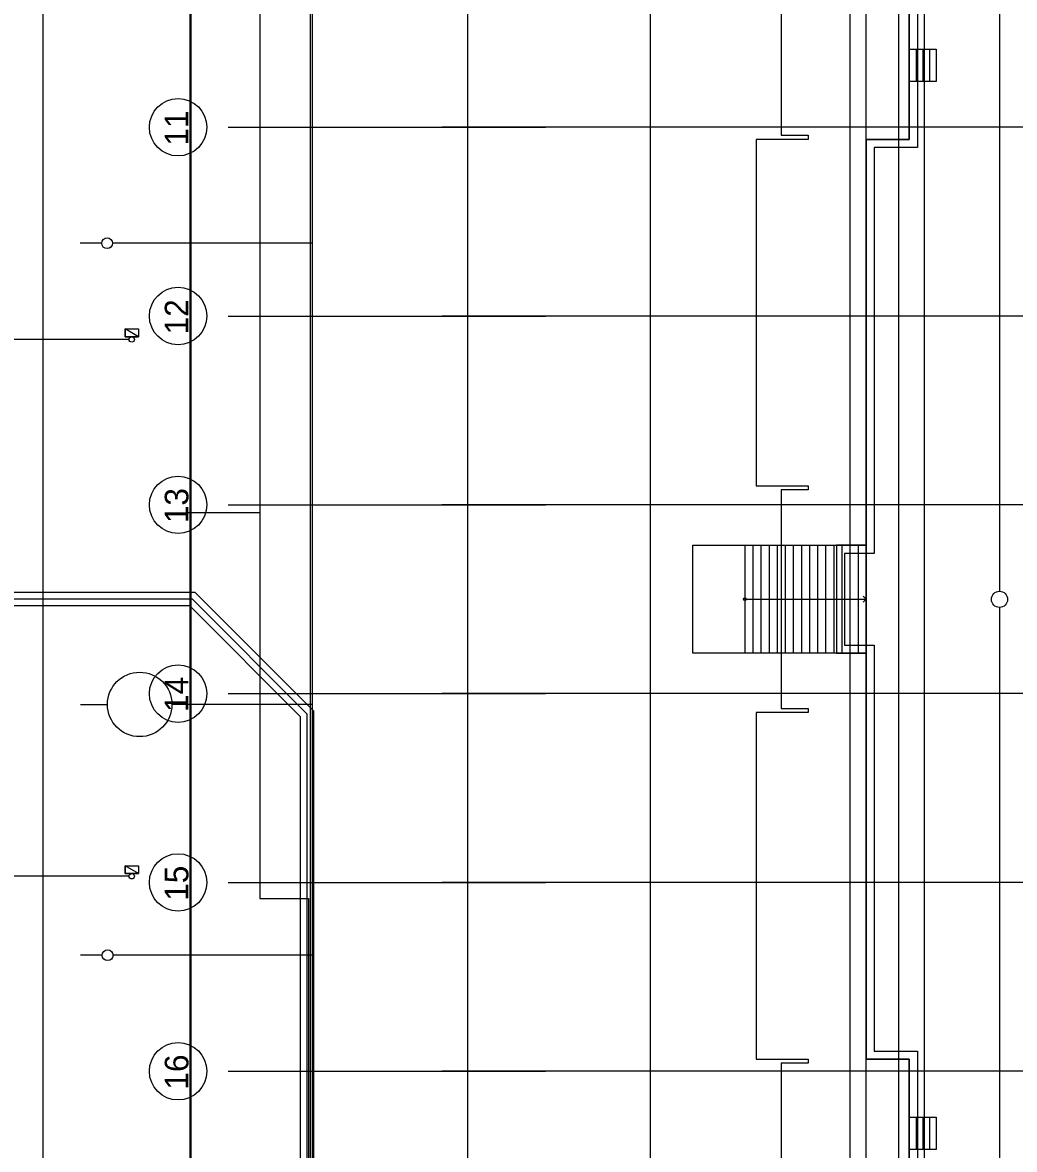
# Model space of a CAD drawing. Extents: x -264222 to -263592, y -1242345 to -1242048.
# Drawn here: x -263924.89 to -263888.12, y -1242184.78 to -1242143 of the extents above; entities that cross this region are included whole.
import ezdxf

# ---------------------------------------------------------------- set-up
doc = ezdxf.new("R2010")
doc.units = 0
for name, color, linetype in [('HESCON_OSI_STAVBY_KFA', 7, 'Continuous'), ('KFA_2D_SITUACIA_DSP', 7, 'Continuous'), ('KFA_SO_62-1_VO_TRASA_KABLOV_PROJEKT', 7, 'Continuous')]:
    doc.layers.add(name, color=color, linetype=linetype)

msp = doc.modelspace()

# ---------------------------------------------------------------- linework, layer by layer
at = {"layer": 'HESCON_OSI_STAVBY_KFA'}
for p, q in [((-263908.393, -1242083.237), (-263908.393, -1242246.707)), ((-263901.618, -1242083.237), (-263901.618, -1242246.707)), ((-263894.218, -1242083.237), (-263894.218, -1242246.707)), ((-263892.418, -1242083.237), (-263892.418, -1242246.707)), ((-263891.468, -1242083.237), (-263891.468, -1242246.707)), ((-263917.265, -1242146.882), (-263905.505, -1242146.882)), ((-263917.265, -1242146.882), (-263905.505, -1242146.882)), ((-263792.653, -1242146.882), (-263909.343, -1242146.882)), ((-263917.265, -1242153.882), (-263905.505, -1242153.882)), ((-263917.265, -1242153.882), (-263905.505, -1242153.882)), ((-263792.653, -1242153.882), (-263909.343, -1242153.882)), ((-263917.265, -1242160.882), (-263905.505, -1242160.882)), ((-263917.265, -1242160.882), (-263905.505, -1242160.882)), ((-263792.653, -1242160.882), (-263909.343, -1242160.882)), ((-263917.265, -1242167.882), (-263905.505, -1242167.882)), ((-263917.265, -1242167.882), (-263905.505, -1242167.882)), ((-263792.653, -1242167.882), (-263909.343, -1242167.882)), ((-263917.265, -1242174.882), (-263905.505, -1242174.882)), ((-263917.265, -1242174.882), (-263905.505, -1242174.882)), ((-263792.653, -1242174.882), (-263909.343, -1242174.882)), ((-263917.265, -1242181.882), (-263905.505, -1242181.882)), ((-263917.265, -1242181.882), (-263905.505, -1242181.882)), ((-263792.653, -1242181.882), (-263909.343, -1242181.882))]:
    msp.add_line(p, q, dxfattribs=at)
for centre in [(-263919.125, -1242146.882), (-263919.125, -1242153.882), (-263919.125, -1242160.882), (-263919.125, -1242167.882), (-263919.125, -1242174.882), (-263919.125, -1242181.882)]:
    msp.add_circle(centre, 1.064, dxfattribs=at)
at = {"layer": 'KFA_2D_SITUACIA_DSP'}
for p, q in [((-263924.143, -1242082.64), (-263924.143, -1242185.14)), ((-263888.673, -1242108.177), (-263888.673, -1242164.087)), ((-263896.768, -1242125.432), (-263896.768, -1242147.182)), ((-263914.218, -1242196.332), (-263914.218, -1242132.432)), ((-263892.018, -1242143.983), (-263891.018, -1242143.983)), ((-263891.768, -1242143.983), (-263891.768, -1242145.181)), ((-263891.518, -1242143.983), (-263891.518, -1242145.181)), ((-263891.268, -1242143.983), (-263891.268, -1242145.181)), ((-263891.018, -1242143.983), (-263891.018, -1242145.181)), ((-263891.018, -1242145.181), (-263892.018, -1242145.181)), ((-263895.768, -1242147.332), (-263897.693, -1242147.332)), ((-263897.693, -1242147.332), (-263897.693, -1242160.182)), ((-263896.768, -1242147.182), (-263895.768, -1242147.182)), ((-263895.768, -1242147.182), (-263895.768, -1242147.332)), ((-263921.957, -1242151.182), (-263922.757, -1242151.182)), ((-263917.093, -1242151.182), (-263921.557, -1242151.182)), ((-263914.143, -1242151.182), (-263917.093, -1242151.182)), ((-263921.093, -1242154.652), (-263921.093, -1242154.362)), ((-263921.093, -1242154.362), (-263920.593, -1242154.362)), ((-263920.593, -1242154.652), (-263921.093, -1242154.362)), ((-263920.593, -1242154.652), (-263921.093, -1242154.362)), ((-263921.093, -1242154.362), (-263921.093, -1242154.652)), ((-263920.593, -1242154.362), (-263920.593, -1242154.652)), ((-263920.944, -1242154.752), (-263926.093, -1242154.752)), ((-263920.593, -1242154.652), (-263921.093, -1242154.652)), ((-263921.093, -1242154.652), (-263920.593, -1242154.652)), ((-263897.693, -1242160.182), (-263895.768, -1242160.182)), ((-263895.768, -1242160.332), (-263896.768, -1242160.332)), ((-263896.768, -1242160.332), (-263896.768, -1242168.432)), ((-263895.768, -1242160.182), (-263895.768, -1242160.332)), ((-263916.093, -1242161.182), (-263918.763, -1242161.182)), ((-263898.118, -1242162.382), (-263898.118, -1242166.382)), ((-263897.818, -1242162.382), (-263897.818, -1242166.382)), ((-263897.518, -1242162.382), (-263897.518, -1242166.382)), ((-263897.218, -1242162.382), (-263897.218, -1242166.382)), ((-263896.918, -1242162.382), (-263896.918, -1242166.382)), ((-263896.618, -1242162.382), (-263896.618, -1242166.382)), ((-263896.318, -1242162.382), (-263896.318, -1242166.382)), ((-263896.018, -1242162.382), (-263896.018, -1242166.382)), ((-263895.718, -1242162.382), (-263895.718, -1242166.382)), ((-263895.418, -1242162.382), (-263895.418, -1242166.382)), ((-263895.118, -1242162.382), (-263895.118, -1242166.382)), ((-263894.818, -1242162.382), (-263894.818, -1242166.382)), ((-263894.518, -1242162.382), (-263894.518, -1242166.382)), ((-263894.218, -1242162.382), (-263894.218, -1242166.382)), ((-263893.918, -1242162.382), (-263893.918, -1242166.382)), ((-263893.618, -1242162.382), (-263893.618, -1242166.382)), ((-263918.489, -1242164.132), (-263946.093, -1242164.132)), ((-263918.593, -1242164.382), (-263946.093, -1242164.382)), ((-263898.118, -1242164.382), (-263893.618, -1242164.382)), ((-263893.618, -1242164.382), (-263893.721, -1242164.274)), ((-263893.618, -1242164.382), (-263893.721, -1242164.491)), ((-263918.696, -1242164.632), (-263946.093, -1242164.632)), ((-263888.673, -1242164.687), (-263888.673, -1242220.396)), ((-263922.745, -1242168.282), (-263921.745, -1242168.282)), ((-263914.143, -1242168.282), (-263919.355, -1242168.282)), ((-263895.768, -1242168.582), (-263897.693, -1242168.582)), ((-263897.693, -1242168.582), (-263897.693, -1242181.432)), ((-263896.768, -1242168.432), (-263895.768, -1242168.432)), ((-263895.768, -1242168.432), (-263895.768, -1242168.582)), ((-263921.093, -1242174.553), (-263921.093, -1242174.263)), ((-263921.093, -1242174.263), (-263920.593, -1242174.263)), ((-263920.593, -1242174.553), (-263921.093, -1242174.263)), ((-263920.593, -1242174.553), (-263921.093, -1242174.263)), ((-263921.093, -1242174.263), (-263921.093, -1242174.553)), ((-263920.593, -1242174.553), (-263921.093, -1242174.553)), ((-263921.093, -1242174.553), (-263920.593, -1242174.553)), ((-263920.593, -1242174.263), (-263920.593, -1242174.553)), ((-263920.944, -1242174.653), (-263925.798, -1242174.653)), ((-263921.938, -1242177.582), (-263922.738, -1242177.582)), ((-263915.293, -1242177.582), (-263921.538, -1242177.582)), ((-263914.143, -1242177.582), (-263915.293, -1242177.582)), ((-263897.693, -1242181.432), (-263895.768, -1242181.432)), ((-263895.768, -1242181.582), (-263896.768, -1242181.582)), ((-263896.768, -1242181.582), (-263896.768, -1242203.332)), ((-263895.768, -1242181.432), (-263895.768, -1242181.582)), ((-263892.018, -1242183.583), (-263891.018, -1242183.583)), ((-263891.768, -1242183.583), (-263891.768, -1242184.781)), ((-263891.518, -1242183.583), (-263891.518, -1242184.781)), ((-263891.268, -1242183.583), (-263891.268, -1242184.781)), ((-263891.018, -1242183.583), (-263891.018, -1242184.781)), ((-263891.018, -1242184.781), (-263892.018, -1242184.781))]:
    msp.add_line(p, q, dxfattribs=at)
for points in [[(-263794.893, -1242227.382), (-263808.968, -1242241.457), (-263894.968, -1242241.457), (-263909.043, -1242227.382), (-263909.043, -1242196.333), (-263914.143, -1242196.333), (-263914.143, -1242132.433), (-263909.043, -1242132.433), (-263909.043, -1242101.382), (-263894.968, -1242087.307), (-263808.968, -1242087.307), (-263794.893, -1242101.382), (-263794.893, -1242227.382)], [(-263892.018, -1242220.33), (-263892.018, -1242181.432), (-263893.618, -1242181.432), (-263893.618, -1242147.332), (-263892.018, -1242147.332), (-263892.018, -1242108.434), (-263891.673, -1242108.09), (-263894.073, -1242107.096), (-263892.937, -1242105.959), (-263896.896, -1242101.999), (-263894.351, -1242099.454), (-263890.391, -1242103.413), (-263889.254, -1242102.277), (-263888.26, -1242104.677), (-263887.916, -1242104.332), (-263816.02, -1242104.332)], [(-263918.593, -1242164.382), (-263914.35, -1242168.625), (-263914.35, -1242199.59), (-263910.108, -1242203.832), (-263891.768, -1242203.832)], [(-263918.489, -1242164.132), (-263914.1, -1242168.521), (-263914.1, -1242199.486), (-263910.004, -1242203.582), (-263891.768, -1242203.582)], [(-263918.696, -1242164.632), (-263914.6, -1242168.728), (-263914.6, -1242199.693), (-263910.211, -1242204.082), (-263891.768, -1242204.082)]]:
    msp.add_lwpolyline(points, dxfattribs=at)
for points in [[(-263816.02, -1242224.432), (-263811.918, -1242220.33), (-263811.918, -1242108.434), (-263816.02, -1242104.332), (-263887.916, -1242104.332), (-263892.018, -1242108.434), (-263892.018, -1242147.332), (-263893.618, -1242147.332), (-263893.618, -1242162.382), (-263894.718, -1242162.382), (-263894.718, -1242166.382), (-263893.618, -1242166.382), (-263893.618, -1242181.432), (-263892.018, -1242181.432), (-263892.018, -1242220.33), (-263887.916, -1242224.432)], [(-263816.144, -1242224.132), (-263812.218, -1242220.206), (-263812.218, -1242108.558), (-263816.144, -1242104.632), (-263887.792, -1242104.632), (-263891.718, -1242108.558), (-263891.718, -1242147.632), (-263893.318, -1242147.632), (-263893.318, -1242162.682), (-263894.418, -1242162.682), (-263894.418, -1242166.082), (-263893.318, -1242166.082), (-263893.318, -1242181.132), (-263891.718, -1242181.132), (-263891.718, -1242220.206), (-263887.792, -1242224.132)], [(-263893.618, -1242118.282), (-263916.093, -1242118.282), (-263916.093, -1242175.482), (-263914.293, -1242175.482), (-263914.293, -1242210.482), (-263893.618, -1242210.482), (-263893.618, -1242166.382), (-263900.043, -1242166.382), (-263900.043, -1242162.382), (-263893.618, -1242162.382)]]:
    msp.add_lwpolyline(points, close=True, dxfattribs=at)
for centre, radius in [((-263921.757, -1242151.182), 0.2), ((-263920.844, -1242154.752), 0.1), ((-263888.673, -1242164.387), 0.3), ((-263898.118, -1242164.382), 0.05), ((-263920.55, -1242168.282), 1.195), ((-263920.844, -1242174.653), 0.1), ((-263921.738, -1242177.582), 0.2)]:
    msp.add_circle(centre, radius, dxfattribs=at)
at = {"layer": 'KFA_SO_62-1_VO_TRASA_KABLOV_PROJEKT'}
for p, q in [((-263918.645, -1242194.9), (-263918.645, -1242084.831)), ((-263918.695, -1242110.308), (-263918.695, -1242194.95))]:
    msp.add_line(p, q, dxfattribs=at)

# ---------------------------------------------------------------- texts
at = {"layer": 'HESCON_OSI_STAVBY_KFA'}
for s, p in [('11', (-263918.744, -1242147.562)), ('12', (-263918.744, -1242154.562)), ('13', (-263918.744, -1242161.562)), ('14', (-263918.744, -1242168.562)), ('15', (-263918.744, -1242175.562)), ('16', (-263918.744, -1242182.562))]:
    msp.add_text(s, height=0.875, rotation=90, dxfattribs=at).set_placement(p)

doc.saveas('drawing.dxf')
